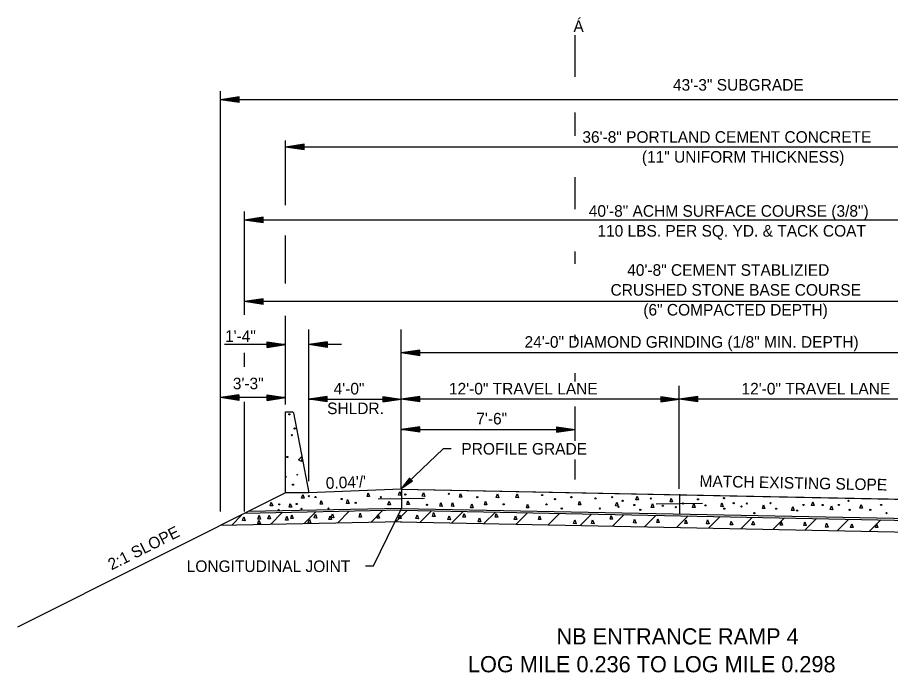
# Model space of a CAD drawing. Extents: x 60325 to 61047, y 53669 to 53767.
# Drawn here: x 60936.48 to 60974.17, y 53715.59 to 53743.86 of the extents above; entities that cross this region are included whole.
import ezdxf

# ---------------------------------------------------------------- set-up
doc = ezdxf.new("R2010")
doc.units = 0
doc.layers.add('R_Border', color=7, linetype='Continuous')
doc.layers.add('R_Border Prem', color=7, linetype='Continuous')

msp = doc.modelspace()

# ---------------------------------------------------------------- linework, layer by layer
at = {"layer": 'R_Border'}
for p, q in [((60953.051, 53727.969), (60953.051, 53730.395)), ((60953.851, 53729.502), (60953.051, 53729.382)), ((60953.851, 53729.262), (60953.051, 53729.382)), ((60977.051, 53729.382), (60953.051, 53729.382)), ((60953.851, 53729.482), (60953.184, 53729.382)), ((60953.851, 53729.282), (60953.184, 53729.382)), ((60953.851, 53729.461), (60953.322, 53729.382)), ((60953.851, 53729.302), (60953.322, 53729.382)), ((60953.851, 53729.441), (60953.455, 53729.382)), ((60953.851, 53729.322), (60953.455, 53729.382)), ((60953.851, 53729.421), (60953.591, 53729.382)), ((60953.851, 53729.343), (60953.591, 53729.382)), ((60953.851, 53729.401), (60953.724, 53729.382)), ((60953.851, 53729.363), (60953.724, 53729.382)), ((60953.851, 53729.262), (60953.851, 53729.502)), ((60953.051, 53723.826), (60953.051, 53727.969)), ((60953.851, 53727.508), (60953.051, 53727.388)), ((60977.051, 53727.388), (60953.051, 53727.388)), ((60953.851, 53727.268), (60953.051, 53727.388)), ((60953.851, 53727.488), (60953.184, 53727.388)), ((60953.851, 53727.288), (60953.184, 53727.388)), ((60953.851, 53727.467), (60953.322, 53727.388)), ((60953.851, 53727.308), (60953.322, 53727.388)), ((60953.851, 53727.447), (60953.455, 53727.388)), ((60953.851, 53727.328), (60953.455, 53727.388)), ((60953.851, 53727.427), (60953.591, 53727.388)), ((60953.851, 53727.349), (60953.591, 53727.388)), ((60953.851, 53727.407), (60953.724, 53727.388)), ((60953.851, 53727.369), (60953.724, 53727.388)), ((60953.851, 53727.268), (60953.851, 53727.508)), ((60964.251, 53727.508), (60965.051, 53727.388)), ((60964.251, 53727.508), (60964.251, 53727.268)), ((60964.251, 53727.488), (60964.917, 53727.388)), ((60964.251, 53727.467), (60964.78, 53727.388)), ((60964.251, 53727.447), (60964.646, 53727.388)), ((60964.251, 53727.427), (60964.511, 53727.388)), ((60964.251, 53727.407), (60964.377, 53727.388)), ((60964.251, 53727.268), (60965.051, 53727.388)), ((60964.251, 53727.349), (60964.511, 53727.388)), ((60964.251, 53727.308), (60964.78, 53727.388)), ((60964.251, 53727.288), (60964.917, 53727.388)), ((60964.251, 53727.328), (60964.646, 53727.388)), ((60964.251, 53727.369), (60964.377, 53727.388)), ((60965.851, 53727.508), (60965.051, 53727.388)), ((60965.851, 53727.268), (60965.051, 53727.388)), ((60965.851, 53727.488), (60965.184, 53727.388)), ((60965.851, 53727.288), (60965.184, 53727.388)), ((60965.851, 53727.467), (60965.322, 53727.388)), ((60965.851, 53727.308), (60965.322, 53727.388)), ((60965.851, 53727.447), (60965.455, 53727.388)), ((60965.851, 53727.328), (60965.455, 53727.388)), ((60965.851, 53727.427), (60965.591, 53727.388)), ((60965.851, 53727.349), (60965.591, 53727.388)), ((60965.851, 53727.407), (60965.724, 53727.388)), ((60965.851, 53727.369), (60965.724, 53727.388)), ((60965.851, 53727.268), (60965.851, 53727.508)), ((60960.549, 53725.674), (60960.549, 53727.075)), ((60953.051, 53723.628), (60953.051, 53724.71)), ((60953.053, 53723.506), (60953.053, 53722.673)), ((60965.053, 53723.289), (60965.053, 53722.456)), ((60953.053, 53723.09), (60952.053, 53723.07)), ((60954.053, 53723.11), (60953.053, 53723.09)), ((60965.053, 53722.872), (60964.053, 53722.852)), ((60966.053, 53722.892), (60965.053, 53722.872)), ((60951.852, 53720.196), (60953.053, 53722.676)), ((60951.505, 53720.196), (60951.852, 53720.196))]:
    msp.add_line(p, q, dxfattribs=at)
msp.add_lwpolyline([(60953.053, 53723.506), (60976.967, 53723.028), (60977.051, 53723.025)], dxfattribs=at)
at = {"layer": 'R_Border Prem'}
for p, q in [((60960.549, 53741.297), (60960.549, 53743.091)), ((60945.245, 53726.543), (60945.245, 53740.686)), ((60946.045, 53740.43), (60945.245, 53740.31)), ((60986.91, 53740.31), (60945.245, 53740.31)), ((60946.045, 53740.19), (60945.245, 53740.31)), ((60946.045, 53740.41), (60945.378, 53740.31)), ((60946.045, 53740.21), (60945.378, 53740.31)), ((60946.045, 53740.39), (60945.516, 53740.31)), ((60946.045, 53740.231), (60945.516, 53740.31)), ((60946.045, 53740.37), (60945.649, 53740.31)), ((60946.045, 53740.251), (60945.649, 53740.31)), ((60946.045, 53740.349), (60945.785, 53740.31)), ((60946.045, 53740.271), (60945.785, 53740.31)), ((60946.045, 53740.329), (60945.918, 53740.31)), ((60946.045, 53740.291), (60945.918, 53740.31)), ((60946.045, 53740.19), (60946.045, 53740.43)), ((60960.549, 53738.75), (60960.549, 53739.757)), ((60948.056, 53735.767), (60948.056, 53738.552)), ((60948.856, 53738.389), (60948.056, 53738.269)), ((60948.856, 53738.369), (60948.19, 53738.269)), ((60948.856, 53738.349), (60948.328, 53738.269)), ((60948.856, 53738.329), (60948.461, 53738.269)), ((60948.856, 53738.149), (60948.856, 53738.389)), ((60984.098, 53738.269), (60948.056, 53738.269)), ((60948.856, 53738.149), (60948.056, 53738.269)), ((60948.856, 53738.169), (60948.19, 53738.269)), ((60948.856, 53738.19), (60948.328, 53738.269)), ((60948.856, 53738.21), (60948.461, 53738.269)), ((60948.856, 53738.308), (60948.596, 53738.269)), ((60948.856, 53738.23), (60948.596, 53738.269)), ((60948.856, 53738.288), (60948.73, 53738.269)), ((60948.856, 53738.25), (60948.73, 53738.269)), ((60960.549, 53735.594), (60960.549, 53736.969)), ((60946.286, 53731.021), (60946.286, 53735.484)), ((60947.086, 53735.237), (60946.286, 53735.117)), ((60985.868, 53735.117), (60946.286, 53735.117)), ((60947.086, 53734.997), (60946.286, 53735.117)), ((60947.086, 53735.217), (60946.42, 53735.117)), ((60947.086, 53735.017), (60946.42, 53735.117)), ((60947.086, 53735.196), (60946.557, 53735.117)), ((60947.086, 53735.037), (60946.557, 53735.117)), ((60947.086, 53735.176), (60946.691, 53735.117)), ((60947.086, 53735.057), (60946.691, 53735.117)), ((60947.086, 53735.156), (60946.826, 53735.117)), ((60947.086, 53735.078), (60946.826, 53735.117)), ((60947.086, 53735.135), (60946.96, 53735.117)), ((60947.086, 53735.098), (60946.96, 53735.117)), ((60947.086, 53734.997), (60947.086, 53735.237)), ((60948.056, 53732.382), (60948.056, 53734.447)), ((60960.549, 53733.224), (60960.549, 53733.759)), ((60947.086, 53731.72), (60946.286, 53731.6)), ((60985.868, 53731.6), (60946.286, 53731.6)), ((60947.086, 53731.48), (60946.286, 53731.6)), ((60947.086, 53731.7), (60946.42, 53731.6)), ((60947.086, 53731.5), (60946.42, 53731.6)), ((60947.086, 53731.68), (60946.557, 53731.6)), ((60947.086, 53731.521), (60946.557, 53731.6)), ((60947.086, 53731.66), (60946.691, 53731.6)), ((60947.086, 53731.541), (60946.691, 53731.6)), ((60947.086, 53731.64), (60946.826, 53731.6)), ((60947.086, 53731.562), (60946.826, 53731.6)), ((60947.086, 53731.619), (60946.96, 53731.6)), ((60947.086, 53731.582), (60946.96, 53731.6)), ((60947.086, 53731.48), (60947.086, 53731.72)), ((60948.056, 53727.154), (60948.056, 53730.991)), ((60949.053, 53723.846), (60949.053, 53730.395)), ((60960.549, 53729.912), (60960.549, 53730.166)), ((60948.056, 53729.741), (60945.412, 53729.741)), ((60947.256, 53729.861), (60948.056, 53729.741)), ((60947.256, 53729.621), (60947.256, 53729.861)), ((60947.256, 53729.841), (60947.923, 53729.741)), ((60947.256, 53729.821), (60947.785, 53729.741)), ((60947.256, 53729.801), (60947.652, 53729.741)), ((60947.256, 53729.78), (60947.516, 53729.741)), ((60947.256, 53729.76), (60947.383, 53729.741)), ((60947.256, 53729.621), (60948.056, 53729.741)), ((60947.256, 53729.702), (60947.516, 53729.741)), ((60947.256, 53729.662), (60947.785, 53729.741)), ((60947.256, 53729.641), (60947.923, 53729.741)), ((60947.256, 53729.682), (60947.652, 53729.741)), ((60947.256, 53729.722), (60947.383, 53729.741)), ((60949.853, 53729.861), (60949.053, 53729.741)), ((60950.467, 53729.741), (60949.053, 53729.741)), ((60949.853, 53729.621), (60949.053, 53729.741)), ((60949.853, 53729.841), (60949.186, 53729.741)), ((60949.853, 53729.641), (60949.186, 53729.741)), ((60949.853, 53729.821), (60949.324, 53729.741)), ((60949.853, 53729.662), (60949.324, 53729.741)), ((60949.853, 53729.801), (60949.457, 53729.741)), ((60949.853, 53729.682), (60949.457, 53729.741)), ((60949.853, 53729.78), (60949.593, 53729.741)), ((60949.853, 53729.702), (60949.593, 53729.741)), ((60949.853, 53729.76), (60949.726, 53729.741)), ((60949.853, 53729.722), (60949.726, 53729.741)), ((60949.853, 53729.861), (60949.853, 53729.621)), ((60946.286, 53728.778), (60946.286, 53729.39)), ((60960.549, 53728.158), (60960.549, 53728.506)), ((60953.051, 53723.526), (60953.051, 53727.969)), ((60965.051, 53723.526), (60965.051, 53727.969)), ((60946.043, 53727.575), (60945.243, 53727.455)), ((60948.054, 53727.455), (60945.243, 53727.455)), ((60946.043, 53727.335), (60945.243, 53727.455)), ((60946.043, 53727.555), (60945.376, 53727.455)), ((60946.043, 53727.355), (60945.376, 53727.455)), ((60946.043, 53727.534), (60945.514, 53727.455)), ((60946.043, 53727.375), (60945.514, 53727.455)), ((60946.043, 53727.514), (60945.647, 53727.455)), ((60946.043, 53727.395), (60945.647, 53727.455)), ((60946.043, 53727.493), (60945.783, 53727.455)), ((60946.043, 53727.415), (60945.783, 53727.455)), ((60946.043, 53727.473), (60945.916, 53727.455)), ((60946.043, 53727.436), (60945.916, 53727.455)), ((60946.043, 53727.575), (60946.043, 53727.335)), ((60947.254, 53727.575), (60948.054, 53727.455)), ((60947.254, 53727.335), (60947.254, 53727.575)), ((60947.254, 53727.555), (60947.921, 53727.455)), ((60947.254, 53727.534), (60947.783, 53727.455)), ((60947.254, 53727.514), (60947.65, 53727.455)), ((60947.254, 53727.494), (60947.514, 53727.455)), ((60947.254, 53727.473), (60947.381, 53727.455)), ((60947.254, 53727.335), (60948.054, 53727.455)), ((60947.254, 53727.416), (60947.514, 53727.455)), ((60947.254, 53727.375), (60947.783, 53727.455)), ((60947.254, 53727.355), (60947.921, 53727.455)), ((60947.254, 53727.395), (60947.65, 53727.455)), ((60947.254, 53727.436), (60947.381, 53727.455)), ((60949.851, 53727.508), (60949.051, 53727.388)), ((60949.851, 53727.268), (60949.051, 53727.388)), ((60949.053, 53727.388), (60953.051, 53727.388)), ((60949.851, 53727.488), (60949.184, 53727.388)), ((60949.851, 53727.288), (60949.184, 53727.388)), ((60949.851, 53727.467), (60949.322, 53727.388)), ((60949.851, 53727.308), (60949.322, 53727.388)), ((60949.851, 53727.447), (60949.455, 53727.388)), ((60949.851, 53727.328), (60949.455, 53727.388)), ((60949.851, 53727.427), (60949.591, 53727.388)), ((60949.851, 53727.349), (60949.591, 53727.388)), ((60949.851, 53727.407), (60949.724, 53727.388)), ((60949.851, 53727.369), (60949.724, 53727.388)), ((60949.851, 53727.268), (60949.851, 53727.508)), ((60952.251, 53727.508), (60953.051, 53727.388)), ((60952.251, 53727.508), (60952.251, 53727.268)), ((60952.251, 53727.488), (60952.917, 53727.388)), ((60952.251, 53727.467), (60952.78, 53727.388)), ((60952.251, 53727.447), (60952.646, 53727.388)), ((60952.251, 53727.427), (60952.511, 53727.388)), ((60952.251, 53727.407), (60952.377, 53727.388)), ((60952.251, 53727.268), (60953.051, 53727.388)), ((60952.251, 53727.349), (60952.511, 53727.388)), ((60952.251, 53727.308), (60952.78, 53727.388)), ((60952.251, 53727.288), (60952.917, 53727.388)), ((60952.251, 53727.328), (60952.646, 53727.388)), ((60952.251, 53727.369), (60952.377, 53727.388)), ((60946.286, 53726.137), (60946.286, 53727.275)), ((60948.056, 53726.847), (60948.334, 53726.847)), ((60948.057, 53723.346), (60948.056, 53726.847)), ((60948.394, 53726.8), (60949.053, 53723.346)), ((60960.549, 53725.587), (60960.549, 53726.726)), ((60945.245, 53722.538), (60945.245, 53726.543)), ((60946.286, 53722.538), (60946.286, 53726.137)), ((60953.851, 53726.201), (60953.051, 53726.081)), ((60953.051, 53726.081), (60960.551, 53726.081)), ((60953.851, 53725.961), (60953.051, 53726.081)), ((60953.851, 53726.181), (60953.184, 53726.081)), ((60953.851, 53725.981), (60953.184, 53726.081)), ((60953.851, 53726.161), (60953.322, 53726.081)), ((60953.851, 53726.002), (60953.322, 53726.081)), ((60953.851, 53726.141), (60953.455, 53726.081)), ((60953.851, 53726.022), (60953.455, 53726.081)), ((60953.851, 53726.121), (60953.591, 53726.081)), ((60953.851, 53726.043), (60953.591, 53726.081)), ((60953.851, 53726.1), (60953.724, 53726.081)), ((60953.851, 53726.063), (60953.724, 53726.081)), ((60953.851, 53725.961), (60953.851, 53726.201)), ((60959.749, 53726.201), (60960.549, 53726.081)), ((60959.749, 53726.201), (60959.749, 53725.961)), ((60959.749, 53726.181), (60960.415, 53726.081)), ((60959.749, 53726.161), (60960.277, 53726.081)), ((60959.749, 53726.141), (60960.144, 53726.081)), ((60959.749, 53726.12), (60960.009, 53726.081)), ((60959.749, 53726.1), (60959.875, 53726.081)), ((60959.749, 53725.961), (60960.549, 53726.081)), ((60959.749, 53726.042), (60960.009, 53726.081)), ((60959.749, 53726.002), (60960.277, 53726.081)), ((60959.749, 53725.981), (60960.415, 53726.081)), ((60959.749, 53726.022), (60960.144, 53726.081)), ((60959.749, 53726.063), (60959.875, 53726.081)), ((60960.549, 53723.917), (60960.549, 53724.779)), ((60953.406, 53723.985), (60953.032, 53723.507)), ((60953.53, 53723.854), (60953.032, 53723.507)), ((60953.416, 53723.974), (60953.105, 53723.576)), ((60953.52, 53723.865), (60953.105, 53723.576)), ((60953.427, 53723.963), (60953.18, 53723.647)), ((60953.509, 53723.876), (60953.18, 53723.647)), ((60953.437, 53723.952), (60953.252, 53723.715)), ((60953.499, 53723.887), (60953.252, 53723.715)), ((60953.448, 53723.941), (60953.326, 53723.785)), ((60953.488, 53723.898), (60953.326, 53723.785)), ((60953.458, 53723.93), (60953.399, 53723.854)), ((60953.478, 53723.909), (60953.399, 53723.854)), ((60953.53, 53723.854), (60953.406, 53723.985)), ((60948.057, 53723.346), (60936.479, 53717.558)), ((60949.053, 53723.346), (60948.057, 53723.346)), ((60949.053, 53723.346), (60948.057, 53723.346)), ((60953.051, 53723.506), (60949.053, 53723.346)), ((60953.05, 53723.506), (60977.051, 53723.026)), ((60953.053, 53722.596), (60946.286, 53722.461)), ((60953.053, 53722.676), (60946.453, 53722.544)), ((60947.404, 53721.983), (60947.914, 53722.494)), ((60948.847, 53722.012), (60949.357, 53722.523)), ((60950.29, 53722.041), (60950.8, 53722.551)), ((60951.733, 53722.07), (60952.244, 53722.58)), ((60952.811, 53722.101), (60953.301, 53722.591)), ((60953.053, 53722.596), (60979.051, 53722.076)), ((60953.054, 53722.676), (60979.051, 53722.156)), ((60953.867, 53722.08), (60954.357, 53722.57)), ((60955.237, 53722.053), (60955.727, 53722.543)), ((60956.62, 53722.025), (60957.11, 53722.515)), ((60958.005, 53721.997), (60958.495, 53722.488)), ((60945.727, 53721.95), (60946.156, 53722.379)), ((60959.389, 53721.97), (60959.879, 53722.46)), ((60960.771, 53721.942), (60961.261, 53722.432)), ((60962.17, 53721.914), (60962.66, 53722.404)), ((60963.556, 53721.886), (60964.046, 53722.377)), ((60964.943, 53721.859), (60965.433, 53722.349)), ((60966.329, 53721.831), (60966.819, 53722.321)), ((60967.715, 53721.803), (60968.206, 53722.293)), ((60969.102, 53721.775), (60969.592, 53722.266)), ((60970.488, 53721.748), (60970.979, 53722.238)), ((60971.875, 53721.72), (60972.365, 53722.21)), ((60973.261, 53721.692), (60973.752, 53722.182)), ((60953.053, 53722.096), (60945.245, 53721.94)), ((60953.011, 53722.097), (60978.968, 53721.578))]:
    msp.add_line(p, q, dxfattribs=at)
for points in [[(60955.207, 53725.24), (60954.862, 53725.24), (60953.032, 53723.507)], [(60948.761, 53724.875), (60948.744, 53724.698), (60948.619, 53724.776), (60948.754, 53724.912)], [(60948.795, 53723.282), (60948.855, 53723.116), (60948.745, 53723.121), (60948.795, 53723.282)], [(60951.62, 53723.349), (60951.68, 53723.183), (60951.57, 53723.188), (60951.62, 53723.349)], [(60952.981, 53723.405), (60953.042, 53723.239), (60952.932, 53723.243), (60952.981, 53723.405)], [(60954.002, 53723.362), (60954.062, 53723.196), (60953.952, 53723.201), (60954.002, 53723.362)], [(60955.608, 53723.32), (60955.669, 53723.154), (60955.559, 53723.158), (60955.608, 53723.32)], [(60957.198, 53723.303), (60957.259, 53723.137), (60957.149, 53723.141), (60957.198, 53723.303)], [(60958.049, 53723.303), (60958.109, 53723.137), (60957.999, 53723.141), (60958.049, 53723.303)], [(60947.439, 53722.947), (60947.5, 53722.781), (60947.39, 53722.785), (60947.439, 53722.947)], [(60948.258, 53722.888), (60948.319, 53722.722), (60948.209, 53722.726), (60948.258, 53722.888)], [(60949.591, 53723.02), (60949.652, 53722.854), (60949.542, 53722.858), (60949.591, 53723.02)], [(60950.734, 53723.054), (60950.794, 53722.888), (60950.684, 53722.893), (60950.734, 53723.054)], [(60952.519, 53722.992), (60952.579, 53722.826), (60952.469, 53722.83), (60952.519, 53722.992)], [(60953.338, 53723.005), (60953.399, 53722.839), (60953.289, 53722.843), (60953.338, 53723.005)], [(60954.758, 53722.928), (60954.819, 53722.762), (60954.709, 53722.767), (60954.758, 53722.928)], [(60955.26, 53722.928), (60955.32, 53722.762), (60955.21, 53722.767), (60955.26, 53722.928)], [(60956.093, 53722.869), (60956.154, 53722.703), (60956.044, 53722.707), (60956.093, 53722.869)], [(60956.685, 53722.992), (60956.745, 53722.826), (60956.635, 53722.83), (60956.685, 53722.992)], [(60958.499, 53722.86), (60958.56, 53722.694), (60958.45, 53722.699), (60958.499, 53722.86)], [(60960.747, 53722.992), (60960.807, 53722.826), (60960.697, 53722.83), (60960.747, 53722.992)], [(60962.353, 53722.945), (60962.414, 53722.779), (60962.304, 53722.784), (60962.353, 53722.945)], [(60963.228, 53723.205), (60963.288, 53723.039), (60963.178, 53723.043), (60963.228, 53723.205)], [(60963.892, 53722.881), (60963.953, 53722.715), (60963.843, 53722.719), (60963.892, 53722.881)], [(60964.702, 53723.124), (60964.763, 53722.958), (60964.653, 53722.962), (60964.702, 53723.124)], [(60965.674, 53722.881), (60965.735, 53722.715), (60965.625, 53722.719), (60965.674, 53722.881)], [(60966.889, 53722.913), (60966.95, 53722.747), (60966.84, 53722.752), (60966.889, 53722.913)], [(60970.81, 53722.962), (60970.87, 53722.796), (60970.76, 53722.8), (60970.81, 53722.962)], [(60954.444, 53722.493), (60954.505, 53722.327), (60954.395, 53722.331), (60954.444, 53722.493)], [(60968.687, 53722.832), (60968.748, 53722.666), (60968.638, 53722.671), (60968.687, 53722.832)], [(60969.951, 53722.751), (60970.012, 53722.585), (60969.902, 53722.59), (60969.951, 53722.751)], [(60971.62, 53722.783), (60971.68, 53722.617), (60971.57, 53722.622), (60971.62, 53722.783)], [(60972.9, 53722.848), (60972.96, 53722.682), (60972.85, 53722.687), (60972.9, 53722.848)], [(60946.25, 53722.31), (60946.31, 53722.144), (60946.2, 53722.148), (60946.25, 53722.31)], [(60946.904, 53722.173), (60946.965, 53722.007), (60946.855, 53722.012), (60946.904, 53722.173)], [(60946.911, 53722.377), (60946.972, 53722.211), (60946.862, 53722.215), (60946.911, 53722.377)], [(60947.344, 53722.385), (60947.404, 53722.219), (60947.294, 53722.224), (60947.344, 53722.385)], [(60948.103, 53722.335), (60948.164, 53722.169), (60948.054, 53722.174), (60948.103, 53722.335)], [(60948.325, 53722.405), (60948.385, 53722.239), (60948.275, 53722.244), (60948.325, 53722.405)], [(60949.081, 53722.207), (60949.141, 53722.041), (60949.031, 53722.046), (60949.081, 53722.207)], [(60949.341, 53722.425), (60949.401, 53722.259), (60949.291, 53722.264), (60949.341, 53722.425)], [(60949.974, 53722.358), (60950.035, 53722.192), (60949.925, 53722.197), (60949.974, 53722.358)], [(60950.073, 53722.44), (60950.133, 53722.274), (60950.023, 53722.279), (60950.073, 53722.44)], [(60951.275, 53722.464), (60951.335, 53722.298), (60951.225, 53722.303), (60951.275, 53722.464)], [(60952.052, 53722.415), (60952.113, 53722.249), (60952.003, 53722.254), (60952.052, 53722.415)], [(60952.984, 53722.399), (60953.044, 53722.233), (60952.934, 53722.238), (60952.984, 53722.399)], [(60953.728, 53722.396), (60953.788, 53722.23), (60953.678, 53722.234), (60953.728, 53722.396)], [(60955.115, 53722.352), (60955.175, 53722.186), (60955.065, 53722.19), (60955.115, 53722.352)], [(60955.761, 53722.459), (60955.822, 53722.293), (60955.712, 53722.297), (60955.761, 53722.459)], [(60956.422, 53722.264), (60956.482, 53722.098), (60956.372, 53722.103), (60956.422, 53722.264)], [(60957.15, 53722.459), (60957.211, 53722.293), (60957.101, 53722.297), (60957.15, 53722.459)], [(60957.976, 53722.36), (60958.037, 53722.194), (60957.927, 53722.199), (60957.976, 53722.36)], [(60959.018, 53722.36), (60959.078, 53722.194), (60958.968, 53722.199), (60959.018, 53722.36)], [(60960.535, 53722.181), (60960.596, 53722.015), (60960.486, 53722.02), (60960.535, 53722.181)], [(60961.309, 53722.181), (60961.369, 53722.015), (60961.259, 53722.02), (60961.309, 53722.181)], [(60962.112, 53722.375), (60962.173, 53722.209), (60962.063, 53722.213), (60962.112, 53722.375)], [(60963.124, 53722.211), (60963.185, 53722.045), (60963.075, 53722.05), (60963.124, 53722.211)], [(60964.128, 53722.227), (60964.189, 53722.061), (60964.079, 53722.066), (60964.128, 53722.227)], [(60965.335, 53722.187), (60965.396, 53722.021), (60965.286, 53722.025), (60965.335, 53722.187)], [(60966.275, 53722.179), (60966.336, 53722.013), (60966.226, 53722.017), (60966.275, 53722.179)], [(60967.296, 53722.13), (60967.356, 53721.964), (60967.246, 53721.969), (60967.296, 53722.13)], [(60968.235, 53722.13), (60968.296, 53721.964), (60968.186, 53721.969), (60968.235, 53722.13)], [(60969.45, 53722.114), (60969.511, 53721.948), (60969.401, 53721.953), (60969.45, 53722.114)], [(60970.471, 53722.098), (60970.531, 53721.932), (60970.421, 53721.936), (60970.471, 53722.098)], [(60971.411, 53722.033), (60971.471, 53721.867), (60971.361, 53721.872), (60971.411, 53722.033)], [(60972.496, 53722.017), (60972.556, 53721.851), (60972.446, 53721.855), (60972.496, 53722.017)], [(60973.565, 53722.017), (60973.626, 53721.851), (60973.516, 53721.855), (60973.565, 53722.017)]]:
    msp.add_lwpolyline(points, dxfattribs=at)
for centre, radius in [((60948.216, 53726.736), 0.0254), ((60948.446, 53726.127), 0.0254), ((60948.325, 53725.838), 0.0254), ((60948.13, 53724.893), 0.0254), ((60948.558, 53724.128), 0.0127), ((60948.376, 53723.701), 0.0254), ((60953.224, 53723.279), 0.025), ((60955.103, 53723.305), 0.025), ((60959.134, 53723.252), 0.025), ((60947.781, 53722.849), 0.025), ((60948.532, 53722.864), 0.025), ((60949.055, 53723.205), 0.025), ((60949.344, 53723.167), 0.025), ((60950.478, 53723.081), 0.025), ((60951.083, 53722.915), 0.025), ((60952.163, 53723.159), 0.025), ((60956.329, 53723.159), 0.025), ((60957.472, 53722.849), 0.025), ((60959.318, 53722.849), 0.025), ((60959.687, 53723.073), 0.025), ((60960.391, 53723.159), 0.025), ((60961.436, 53723.107), 0.025), ((60962.151, 53723.164), 0.025), ((60962.605, 53723.002), 0.025), ((60963.82, 53723.1), 0.025), ((60965.213, 53722.889), 0.025), ((60965.861, 53723.067), 0.025), ((60966.979, 53723.116), 0.025), ((60967.4, 53722.905), 0.025), ((60967.967, 53722.889), 0.025), ((60968.988, 53722.905), 0.025), ((60972.357, 53723.002), 0.025), ((60947.755, 53722.598), 0.025), ((60948.743, 53722.661), 0.025), ((60949.907, 53722.671), 0.025), ((60954.159, 53722.828), 0.025), ((60959.974, 53722.669), 0.025), ((60961.621, 53722.674), 0.025), ((60962.427, 53722.743), 0.025), ((60963.107, 53722.824), 0.025), ((60963.366, 53722.614), 0.025), ((60964.338, 53722.792), 0.025), ((60964.905, 53722.727), 0.025), ((60966.185, 53722.808), 0.025), ((60966.995, 53722.662), 0.025), ((60967.74, 53722.759), 0.025), ((60968.291, 53722.468), 0.025), ((60969.231, 53722.662), 0.025), ((60970.138, 53722.581), 0.025), ((60970.413, 53722.824), 0.025), ((60971.24, 53722.824), 0.025), ((60971.936, 53722.824), 0.025), ((60972.406, 53722.614), 0.025), ((60973.297, 53722.614), 0.025), ((60973.767, 53722.824), 0.025), ((60973.994, 53722.468), 0.025)]:
    msp.add_circle(centre, radius, dxfattribs=at)
msp.add_arc((60948.059, 53724.043), 0.0254, 264.1751, 95.8413, dxfattribs=at)
msp.add_ellipse((60948.334, 53726.786), major_axis=(0, 0.0619), ratio=0.9997, start_param=4.902487, end_param=6.283185, dxfattribs=at)

# ---------------------------------------------------------------- texts
at = {"layer": 'R_Border'}
for s, height, p in [('24\'-0" DIAMOND GRINDING (1/8" MIN. DEPTH)', 0.5, (60958.37, 53729.608)), ('12\'-0" TRAVEL LANE', 0.5, (60955.107, 53727.592)), ('12\'-0" TRAVEL LANE', 0.5, (60967.736, 53727.592)), ('LONGITUDINAL JOINT', 0.5, (60943.787, 53719.931)), ('NB ENTRANCE RAMP 4', 0.7, (60959.751, 53716.804)), ('LOG MILE 0.236 TO LOG MILE 0.298', 0.7, (60955.929, 53715.604))]:
    msp.add_text(s, height=height, dxfattribs=at).set_placement(p)
msp.add_text('MATCH EXISTING SLOPE', height=0.5, rotation=358.8542, dxfattribs=at).set_placement((60965.921, 53723.608))
at = {"layer": 'R_Border Prem'}
for s, p in [('Á', (60960.481, 53743.229)), ('43\'-3" SUBGRADE', (60964.778, 53740.701)), ('36\'-8" PORTLAND CEMENT CONCRETE', (60960.867, 53738.452)), ('(11" UNIFORM THICKNESS)', (60963.435, 53737.594)), ('40\'-8" ACHM SURFACE COURSE (3/8")', (60961.144, 53735.26)), ('110 LBS. PER SQ. YD. & TACK COAT', (60961.515, 53734.403)), ('40\'-8" CEMENT STABLIZIED', (60962.803, 53732.712)), ('CRUSHED STONE BASE COURSE', (60962.084, 53731.854)), ('(6" COMPACTED DEPTH)', (60963.498, 53730.997)), ('1\'-4"', (60945.44, 53729.86)), ('3\'-3"', (60945.776, 53727.816)), ('4\'-0"', (60950.129, 53727.593)), ('SHLDR.', (60949.848, 53726.743)), ('7\'-6"', (60956.288, 53726.3)), ('PROFILE GRADE', (60955.643, 53724.998))]:
    msp.add_text(s, height=0.5, dxfattribs=at).set_placement(p)
for s, rotation, p in [("0.04'/'", 2.2906, (60949.8, 53723.516)), ('2:1 SLOPE', 26.5651, (60940.542, 53719.998))]:
    msp.add_text(s, height=0.5, rotation=rotation, dxfattribs=at).set_placement(p)

doc.saveas('drawing.dxf')
